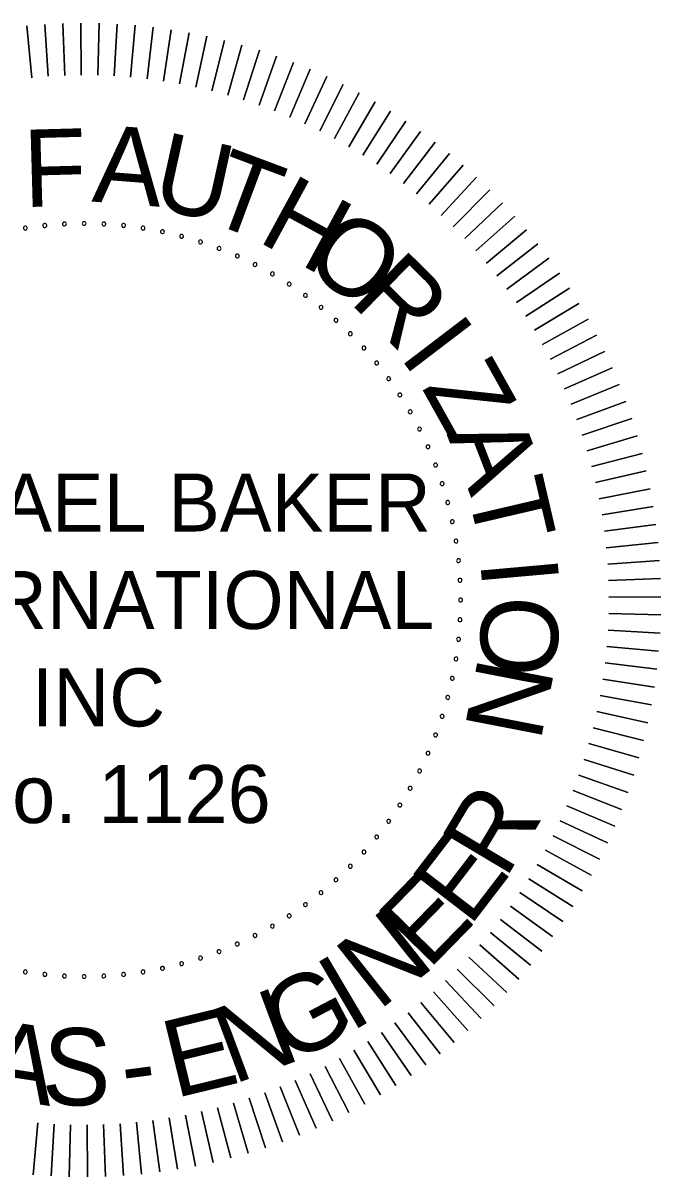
# Model space of a CAD drawing. Extents: x 152 to 3426, y 67 to 2142.
# Drawn here: x 2822.6 to 2960.3, y 307.8 to 556.7 of the extents above; entities that cross this region are included whole.
import ezdxf

# ---------------------------------------------------------------- set-up
doc = ezdxf.new("R2010")
doc.units = 0
doc.layers.add('G-ANNO-TEXT', color=7, linetype='Continuous')

msp = doc.modelspace()

# ---------------------------------------------------------------- linework, layer by layer
at = {"layer": 'G-ANNO-TEXT'}
for points in [[(2824.55, 544.9), (2823.43, 556.07)], [(2823.43, 556.07), (2824.55, 544.9)], [(2828.09, 545.2), (2827.33, 556.4)], [(2827.33, 556.4), (2828.09, 545.2)], [(2831.64, 545.39), (2831.23, 556.6)], [(2831.23, 556.6), (2831.64, 545.39)], [(2835.2, 545.46), (2835.14, 556.68)], [(2835.14, 556.68), (2835.2, 545.46)], [(2838.76, 545.43), (2839.05, 556.64)], [(2839.05, 556.64), (2838.76, 545.43)], [(2842.31, 545.28), (2842.95, 556.48)], [(2842.95, 556.48), (2842.31, 545.28)], [(2845.86, 545.02), (2846.85, 556.2)], [(2846.85, 556.2), (2845.86, 545.02)], [(2849.39, 544.65), (2850.74, 555.79)], [(2850.74, 555.79), (2849.39, 544.65)], [(2852.92, 544.17), (2854.61, 555.26)], [(2854.61, 555.26), (2852.92, 544.17)], [(2856.43, 543.57), (2858.47, 554.61)], [(2858.47, 554.61), (2856.43, 543.57)], [(2859.91, 542.87), (2862.3, 553.84)], [(2862.3, 553.84), (2859.91, 542.87)], [(2863.38, 542.06), (2866.11, 552.95)], [(2866.11, 552.95), (2863.38, 542.06)], [(2866.81, 541.14), (2869.88, 551.94)], [(2869.88, 551.94), (2866.81, 541.14)], [(2870.22, 540.12), (2873.63, 550.81)], [(2873.63, 550.81), (2870.22, 540.12)], [(2873.59, 538.98), (2877.33, 549.56)], [(2877.33, 549.56), (2873.59, 538.98)], [(2876.92, 537.74), (2881, 548.2)], [(2881, 548.2), (2876.92, 537.74)], [(2880.22, 536.4), (2884.62, 546.73)], [(2884.62, 546.73), (2880.22, 536.4)], [(2883.47, 534.96), (2888.19, 545.14)], [(2888.19, 545.14), (2883.47, 534.96)], [(2886.67, 533.41), (2891.71, 543.44)], [(2891.71, 543.44), (2886.67, 533.41)], [(2889.82, 531.76), (2895.17, 541.63)], [(2895.17, 541.63), (2889.82, 531.76)], [(2892.92, 530.02), (2898.58, 539.71)], [(2898.58, 539.71), (2892.92, 530.02)], [(2895.96, 528.18), (2901.92, 537.68)], [(2901.92, 537.68), (2895.96, 528.18)], [(2898.95, 526.24), (2905.2, 535.56)], [(2905.2, 535.56), (2898.95, 526.24)], [(2901.87, 524.21), (2908.41, 533.33)], [(2908.41, 533.33), (2901.87, 524.21)], [(2904.72, 522.09), (2911.55, 531)], [(2911.55, 531), (2904.72, 522.09)], [(2907.51, 519.88), (2914.62, 528.57)], [(2914.62, 528.57), (2907.51, 519.88)], [(2910.23, 517.59), (2917.6, 526.05)], [(2917.6, 526.05), (2910.23, 517.59)], [(2920.51, 523.43), (2912.87, 515.21)], [(2912.87, 515.21), (2920.51, 523.43)], [(2923.33, 520.73), (2915.44, 512.75)], [(2915.44, 512.75), (2923.33, 520.73)], [(2926.07, 517.94), (2917.93, 510.21)], [(2917.93, 510.21), (2926.07, 517.94)], [(2928.72, 515.06), (2920.34, 507.59)], [(2920.34, 507.59), (2928.72, 515.06)], [(2931.27, 512.1), (2922.66, 504.9)], [(2922.66, 504.9), (2931.27, 512.1)], [(2933.73, 509.06), (2924.9, 502.14)], [(2924.9, 502.14), (2933.73, 509.06)], [(2936.1, 505.95), (2927.05, 499.3)], [(2927.05, 499.3), (2936.1, 505.95)], [(2938.36, 502.76), (2929.12, 496.4)], [(2929.12, 496.4), (2938.36, 502.76)], [(2940.53, 499.51), (2931.09, 493.44)], [(2931.09, 493.44), (2940.53, 499.51)], [(2942.59, 496.19), (2932.96, 490.42)], [(2932.96, 490.42), (2942.59, 496.19)], [(2944.54, 492.8), (2934.74, 487.34)], [(2934.74, 487.34), (2944.54, 492.8)], [(2946.39, 489.36), (2936.42, 484.21)], [(2936.42, 484.21), (2946.39, 489.36)], [(2948.13, 485.86), (2938, 481.02)], [(2938, 481.02), (2948.13, 485.86)], [(2949.76, 482.3), (2939.49, 477.79)], [(2939.49, 477.79), (2949.76, 482.3)], [(2951.28, 478.7), (2940.87, 474.51)], [(2940.87, 474.51), (2951.28, 478.7)], [(2952.68, 475.05), (2942.14, 471.19)], [(2942.14, 471.19), (2952.68, 475.05)], [(2953.97, 471.36), (2943.31, 467.83)], [(2943.31, 467.83), (2953.97, 471.36)], [(2955.14, 467.63), (2944.38, 464.44)], [(2944.38, 464.44), (2955.14, 467.63)], [(2956.19, 463.86), (2945.33, 461.01)], [(2945.33, 461.01), (2956.19, 463.86)], [(2957.12, 460.07), (2946.18, 457.56)], [(2946.18, 457.56), (2957.12, 460.07)], [(2957.94, 456.24), (2946.92, 454.08)], [(2946.92, 454.08), (2957.94, 456.24)], [(2958.63, 452.4), (2947.56, 450.58)], [(2947.56, 450.58), (2958.63, 452.4)], [(2959.2, 448.53), (2948.08, 447.06)], [(2948.08, 447.06), (2959.2, 448.53)], [(2959.65, 444.65), (2948.49, 443.53)], [(2948.49, 443.53), (2959.65, 444.65)], [(2959.98, 440.75), (2948.78, 439.98)], [(2948.78, 439.98), (2959.98, 440.75)], [(2960.19, 436.85), (2948.97, 436.43)], [(2948.97, 436.43), (2960.19, 436.85)], [(2960.27, 432.94), (2949.05, 432.88)], [(2949.05, 432.88), (2960.27, 432.94)], [(2960.23, 429.03), (2949.01, 429.32)], [(2949.01, 429.32), (2960.23, 429.03)], [(2960.07, 425.12), (2948.86, 425.77)], [(2948.86, 425.77), (2960.07, 425.12)], [(2959.78, 421.22), (2948.6, 422.22)], [(2948.6, 422.22), (2959.78, 421.22)], [(2959.38, 417.34), (2948.23, 418.68)], [(2948.23, 418.68), (2959.38, 417.34)], [(2958.85, 413.46), (2947.75, 415.16)], [(2947.75, 415.16), (2958.85, 413.46)], [(2958.2, 409.61), (2947.16, 411.65)], [(2947.16, 411.65), (2958.2, 409.61)], [(2957.42, 405.78), (2946.46, 408.16)], [(2946.46, 408.16), (2957.42, 405.78)], [(2956.53, 401.97), (2945.65, 404.7)], [(2945.65, 404.7), (2956.53, 401.97)], [(2955.52, 398.19), (2944.73, 401.26)], [(2944.73, 401.26), (2955.52, 398.19)], [(2954.39, 394.45), (2943.7, 397.86)], [(2943.7, 397.86), (2954.39, 394.45)], [(2953.15, 390.75), (2942.57, 394.49)], [(2942.57, 394.49), (2953.15, 390.75)], [(2951.79, 387.08), (2941.33, 391.15)], [(2941.33, 391.15), (2951.79, 387.08)], [(2950.31, 383.46), (2939.99, 387.86)], [(2939.99, 387.86), (2950.31, 383.46)], [(2948.72, 379.89), (2938.54, 384.61)], [(2938.54, 384.61), (2948.72, 379.89)], [(2947.02, 376.37), (2936.99, 381.41)], [(2936.99, 381.41), (2947.02, 376.37)], [(2945.21, 372.9), (2935.35, 378.26)], [(2935.35, 378.26), (2945.21, 372.9)], [(2943.29, 369.5), (2933.6, 375.16)], [(2933.6, 375.16), (2943.29, 369.5)], [(2941.27, 366.15), (2931.76, 372.11)], [(2931.76, 372.11), (2941.27, 366.15)], [(2939.14, 362.87), (2929.83, 369.13)], [(2929.83, 369.13), (2939.14, 362.87)], [(2936.91, 359.66), (2927.8, 366.21)], [(2927.8, 366.21), (2936.91, 359.66)], [(2934.58, 356.52), (2925.68, 363.35)], [(2925.68, 363.35), (2934.58, 356.52)], [(2932.16, 353.46), (2923.47, 360.56)], [(2923.47, 360.56), (2932.16, 353.46)], [(2929.63, 350.47), (2921.17, 357.85)], [(2921.17, 357.85), (2929.63, 350.47)], [(2927.02, 347.57), (2918.79, 355.2)], [(2918.79, 355.2), (2927.02, 347.57)], [(2924.31, 344.74), (2916.33, 352.63)], [(2916.33, 352.63), (2924.31, 344.74)], [(2921.52, 342.01), (2913.79, 350.15)], [(2913.79, 350.15), (2921.52, 342.01)], [(2918.64, 339.36), (2911.18, 347.74)], [(2911.18, 347.74), (2918.64, 339.36)], [(2915.69, 336.81), (2908.48, 345.41)], [(2908.48, 345.41), (2915.69, 336.81)], [(2909.54, 331.98), (2902.89, 341.02)], [(2902.89, 341.02), (2909.54, 331.98)], [(2912.65, 334.34), (2905.72, 343.17)], [(2905.72, 343.17), (2912.65, 334.34)], [(2906.35, 329.71), (2899.99, 338.96)], [(2899.99, 338.96), (2906.35, 329.71)], [(2903.09, 327.55), (2897.03, 336.99)], [(2897.03, 336.99), (2903.09, 327.55)], [(2899.77, 325.49), (2894.01, 335.12)], [(2894.01, 335.12), (2899.77, 325.49)], [(2892.94, 321.68), (2887.79, 331.65)], [(2887.79, 331.65), (2892.94, 321.68)], [(2896.39, 323.53), (2890.93, 333.34)], [(2890.93, 333.34), (2896.39, 323.53)], [(2885.89, 318.32), (2881.37, 328.59)], [(2881.37, 328.59), (2885.89, 318.32)], [(2889.44, 319.94), (2884.61, 330.07)], [(2884.61, 330.07), (2889.44, 319.94)], [(2882.28, 316.8), (2878.1, 327.21)], [(2878.1, 327.21), (2882.28, 316.8)], [(2871.21, 312.94), (2868.02, 323.7)], [(2868.02, 323.7), (2871.21, 312.94)], [(2874.94, 314.11), (2871.42, 324.76)], [(2871.42, 324.76), (2874.94, 314.11)], [(2878.64, 315.4), (2874.78, 325.94)], [(2874.78, 325.94), (2878.64, 315.4)], [(2859.83, 310.14), (2857.67, 321.15)], [(2857.67, 321.15), (2859.83, 310.14)], [(2863.65, 310.95), (2861.14, 321.89)], [(2861.14, 321.89), (2863.65, 310.95)], [(2867.45, 311.89), (2864.6, 322.74)], [(2864.6, 322.74), (2867.45, 311.89)], [(2824.81, 308.29), (2825.8, 319.47)], [(2825.8, 319.47), (2824.81, 308.29)], [(2828.71, 308.01), (2829.35, 319.21)], [(2829.35, 319.21), (2828.71, 308.01)], [(2832.62, 307.85), (2832.91, 319.06)], [(2832.91, 319.06), (2832.62, 307.85)], [(2836.52, 307.81), (2836.46, 319.03)], [(2836.46, 319.03), (2836.52, 307.81)], [(2840.43, 307.89), (2840.02, 319.1)], [(2840.02, 319.1), (2840.43, 307.89)], [(2844.34, 308.09), (2843.57, 319.29)], [(2843.57, 319.29), (2844.34, 308.09)], [(2848.23, 308.42), (2847.11, 319.59)], [(2847.11, 319.59), (2848.23, 308.42)], [(2852.12, 308.87), (2850.65, 320)], [(2850.65, 320), (2852.12, 308.87)], [(2855.98, 309.45), (2854.17, 320.52)], [(2854.17, 320.52), (2855.98, 309.45)]]:
    msp.add_lwpolyline(points, dxfattribs=at)
for centre, start, end in [((2823.13, 512.46), 9, 189), ((2827.34, 513.02), 6, 186), ((2827.34, 513.02), 186, 6), ((2831.58, 513.35), 3, 183), ((2831.58, 513.35), 183, 3), ((2835.83, 513.46), 0, 180), ((2835.83, 513.46), 180, 0), ((2840.08, 513.35), 177, 357), ((2840.08, 513.35), 357, 177), ((2844.32, 513.02), 174, 354), ((2844.32, 513.02), 354, 174), ((2848.54, 512.46), 351, 171), ((2823.13, 512.46), 189, 9), ((2848.54, 512.46), 171, 351), ((2852.72, 511.69), 168, 348), ((2852.72, 511.69), 348, 168), ((2856.85, 510.69), 165, 345), ((2856.85, 510.69), 345, 165), ((2860.93, 509.48), 162, 342), ((2860.93, 509.48), 342, 162), ((2864.94, 508.07), 159, 339), ((2864.94, 508.07), 339, 159), ((2868.86, 506.44), 156, 336), ((2868.86, 506.44), 336, 156), ((2872.7, 504.61), 153, 333), ((2872.7, 504.61), 333, 153), ((2876.44, 502.58), 150, 330), ((2876.44, 502.58), 330, 150), ((2880.06, 500.36), 147, 327), ((2880.06, 500.36), 327, 147), ((2883.57, 497.95), 144, 324), ((2883.57, 497.95), 324, 144), ((2886.94, 495.36), 141, 321), ((2886.94, 495.36), 321, 141), ((2890.17, 492.6), 138, 318), ((2890.17, 492.6), 318, 138), ((2893.26, 489.67), 135, 315), ((2893.26, 489.67), 315, 135), ((2896.19, 486.59), 132, 312), ((2896.19, 486.59), 312, 132), ((2898.95, 483.36), 129, 309), ((2898.95, 483.36), 309, 129), ((2901.54, 479.98), 306, 126), ((2901.54, 479.98), 126, 306), ((2903.94, 476.48), 123, 303), ((2903.94, 476.48), 303, 123), ((2906.16, 472.85), 120, 300), ((2906.16, 472.85), 300, 120), ((2908.19, 469.12), 117, 297), ((2908.19, 469.12), 297, 117), ((2910.02, 465.28), 114, 294), ((2910.02, 465.28), 294, 114), ((2911.65, 461.35), 111, 291), ((2911.65, 461.35), 291, 111), ((2913.07, 457.34), 108, 288), ((2913.07, 457.34), 288, 108), ((2914.28, 453.27), 105, 285), ((2914.28, 453.27), 285, 105), ((2915.27, 449.13), 102, 282), ((2915.27, 449.13), 282, 102), ((2916.05, 444.95), 99, 279), ((2916.05, 444.95), 279, 99), ((2916.6, 440.73), 96, 276), ((2916.6, 440.73), 276, 96), ((2916.93, 436.5), 93, 273), ((2916.93, 436.5), 273, 93), ((2917.05, 432.25), 90, 270), ((2917.05, 432.25), 270, 90), ((2916.93, 427.99), 87, 267), ((2916.93, 427.99), 267, 87), ((2916.6, 423.76), 84, 264), ((2916.6, 423.76), 264, 84), ((2916.05, 419.54), 81, 261), ((2916.05, 419.54), 261, 81), ((2915.27, 415.36), 78, 258), ((2915.27, 415.36), 258, 78), ((2914.28, 411.23), 75, 255), ((2914.28, 411.23), 255, 75), ((2913.07, 407.15), 72, 252), ((2913.07, 407.15), 252, 72), ((2911.65, 403.14), 69, 249), ((2911.65, 403.14), 249, 69), ((2910.02, 399.21), 66, 246), ((2910.02, 399.21), 246, 66), ((2908.19, 395.37), 63, 243), ((2908.19, 395.37), 243, 63), ((2906.16, 391.64), 60, 240), ((2906.16, 391.64), 240, 60), ((2903.94, 388.01), 57, 237), ((2903.94, 388.01), 237, 57), ((2901.54, 384.51), 54, 234), ((2901.54, 384.51), 234, 54), ((2898.95, 381.14), 51, 231), ((2898.95, 381.14), 231, 51), ((2896.19, 377.9), 48, 228), ((2896.19, 377.9), 228, 48), ((2893.26, 374.82), 45, 225), ((2893.26, 374.82), 225, 45), ((2890.17, 371.89), 42, 222), ((2890.17, 371.89), 222, 42), ((2886.94, 369.13), 39, 219), ((2886.94, 369.13), 219, 39), ((2883.57, 366.54), 36, 216), ((2883.57, 366.54), 216, 36), ((2880.06, 364.13), 33, 213), ((2880.06, 364.13), 213, 33), ((2876.44, 361.91), 30, 210), ((2876.44, 361.91), 210, 30), ((2868.86, 358.05), 24, 204), ((2872.7, 359.88), 27, 207), ((2872.7, 359.88), 207, 27), ((2864.94, 356.42), 21, 201), ((2864.94, 356.42), 201, 21), ((2868.86, 358.05), 204, 24), ((2856.85, 353.8), 15, 195), ((2856.85, 353.8), 195, 15), ((2860.93, 355.01), 18, 198), ((2860.93, 355.01), 198, 18), ((2823.13, 352.03), 351, 171), ((2823.13, 352.03), 171, 351), ((2827.34, 351.48), 174, 354), ((2827.34, 351.48), 354, 174), ((2831.58, 351.14), 357, 177), ((2831.58, 351.14), 177, 357), ((2835.83, 351.03), 0, 180), ((2835.83, 351.03), 180, 0), ((2840.08, 351.14), 3, 183), ((2840.08, 351.14), 183, 3), ((2844.32, 351.48), 6, 186), ((2844.32, 351.48), 186, 6), ((2848.54, 352.03), 9, 189), ((2848.54, 352.03), 189, 9), ((2852.72, 352.81), 12, 192), ((2852.72, 352.81), 192, 12)]:
    msp.add_arc(centre, 0.417, start, end, dxfattribs=at)

# ---------------------------------------------------------------- texts
for s, rotation, p in [('F', 1.5867, (2822.9, 516.98)), ('A', 355.5955, (2837.35, 518.2)), ('U', 347.5481, (2849.96, 517.01)), ('T', 339.5007, (2861.6, 514.23)), ('H', 331.4533, (2872.9, 509.78)), ('O', 323.4059, (2882.47, 504.51)), ('R', 315.3585, (2892.8, 496.6)), ('I', 307.3112, (2903.63, 484.86)), ('Z', 299.2638, (2908.53, 478.07)), ('A', 291.2164, (2913.99, 468.05)), ('T', 283.169, (2918.35, 456.25)), ('I', 275.1216, (2921.24, 440.66)), ('O', 267.0743, (2921.83, 433.49)), ('N', 259.0269, (2920.95, 420.39)), ('R', 59.2262, (2926.7, 371.8)), ('E', 52.4765, (2918.96, 361.54)), ('E', 45.7268, (2910.08, 352.26)), ('N', 38.4196, (2899.3, 343.47)), ('I', 30.5495, (2893.25, 338.88)), ('G', 27.7404, (2880.07, 331.88)), ('N', 20.4332, (2867.94, 327.68)), ('E', 13.6835, (2855.38, 324.74)), ('A', 351.1991, (2813.78, 325.36)), ('S', 357.9489, (2826.49, 323.51)), ('-', 7.5077, (2844.68, 323.47))]:
    msp.add_text(s, height=16.67, rotation=rotation, dxfattribs=at).set_placement(p)
for s, height, p in [('MICHAEL BAKER', 12.5016, (2775, 447.02)), (' INTERNATIONAL', 12.5016, (2772.99, 426)), ('INC', 12.502, (2824.51, 404.98)), (' No. 1126', 12.502, (2803.57, 384.14))]:
    msp.add_text(s, height=height, dxfattribs=at).set_placement(p)

doc.saveas('drawing.dxf')
